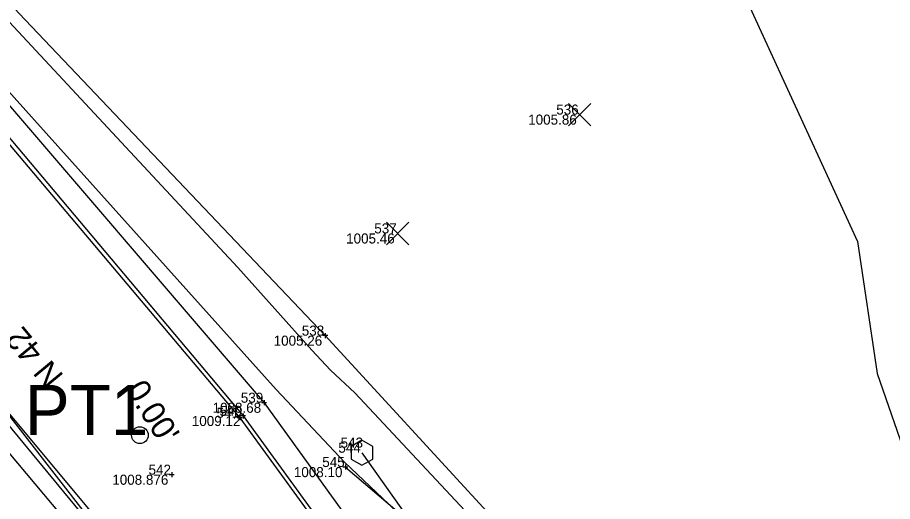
# Model space of a CAD drawing. Extents: x 2354693 to 2355622, y 637071 to 710080.
# Drawn here: x 2355257.5 to 2355361.9, y 709433.1 to 709490.9 of the extents above; entities that cross this region are included whole.
import ezdxf

# ---------------------------------------------------------------- set-up
doc = ezdxf.new("R2010")
doc.units = 0
for name, color, linetype in [('Default', 7, 'Continuous'), ('DT_X_Contour_Minor', 7, 'Continuous'), ('PM_X_Surveyed_Line', 7, 'Continuous'), ('PV_X_EOP', 7, 'Continuous'), ('PV_X_Shoulder', 7, 'Continuous'), ('RD_X_Cells', 7, 'Continuous'), ('RD_X_GR_Lt', 7, 'Continuous'), ('SV_X_Random_Point', 7, 'Continuous'), ('SV_X_Shot_Marker', 7, 'Continuous'), ('SV_X_Text_Elevation', 7, 'Continuous'), ('SV_X_Text_Name', 7, 'Continuous'), ('SV_X_Toe_of_Slope', 7, 'Continuous'), ('SV_X_Top_of_Bank', 7, 'Continuous')]:
    doc.layers.add(name, color=color, linetype=linetype)

msp = doc.modelspace()

# ---------------------------------------------------------------- linework, layer by layer
at = {"layer": 'Default'}
msp.add_line((2355272.1, 709441.07), (2355272.1, 709441.07), dxfattribs=at)
msp.add_line((2355272.1, 709441.07), (2355272.1, 709441.07), dxfattribs=at)
msp.add_line((2355272.1, 709441.07), (2355272.1, 709441.07), dxfattribs=at)
msp.add_line((2355272.1, 709441.07), (2355272.1, 709441.07), dxfattribs=at)
msp.add_line((2355272.1, 709441.07), (2355272.1, 709441.07), dxfattribs=at)
msp.add_line((2355272.1, 709441.07), (2355272.1, 709441.07), dxfattribs=at)
msp.add_line((2355272.1, 709441.07), (2355272.1, 709441.07), dxfattribs=at)
msp.add_line((2355272.1, 709441.07), (2355272.1, 709441.07), dxfattribs=at)
msp.add_line((2355272.1, 709441.07), (2355272.1, 709441.07), dxfattribs=at)
msp.add_circle((2355272.1, 709441.07), 1, dxfattribs=at)
msp.add_circle((2355272.1, 709441.07), 1, dxfattribs=at)
msp.add_circle((2355272.1, 709441.07), 1, dxfattribs=at)
msp.add_circle((2355272.1, 709441.07), 1, dxfattribs=at)
msp.add_circle((2355272.1, 709441.07), 1, dxfattribs=at)
msp.add_circle((2355272.1, 709441.07), 1, dxfattribs=at)
at = {"layer": 'DT_X_Contour_Minor'}
for points in [[(2355344.22, 709493.66), (2355357.75, 709464.2), (2355360.11, 709448.43), (2355366.16, 709430.88), (2355356.05, 709415.12), (2355353.08, 709410.6), (2355352.99, 709409.49), (2355367.98, 709382.49)], [(2355344.22, 709493.66), (2355357.75, 709464.2), (2355360.11, 709448.43), (2355366.16, 709430.88), (2355356.05, 709415.12), (2355353.08, 709410.6), (2355352.99, 709409.49), (2355367.98, 709382.49)], [(2355256.51, 709490.43), (2355283.78, 709461.07), (2355292.63, 709451.21), (2355294.84, 709448.84), (2355297.75, 709446.11), (2355326.87, 709414.97), (2355331.39, 709409.92), (2355333.44, 709407.02), (2355350.91, 709376.42), (2355352.7, 709372.84), (2355354.66, 709368.36), (2355356.55, 709363.93), (2355356.79, 709361.93), (2355357.35, 709361.56), (2355357.12, 709361.28), (2355355.25, 709356.87), (2355352.27, 709351.48), (2355351.87, 709350.82), (2355351.59, 709350.68), (2355350.01, 709351.03), (2355346.35, 709350.2), (2355339.67, 709347.25)], [(2355256.51, 709490.43), (2355283.78, 709461.07), (2355292.63, 709451.21), (2355294.84, 709448.84), (2355297.75, 709446.11), (2355326.87, 709414.97), (2355331.39, 709409.92), (2355333.44, 709407.02), (2355350.91, 709376.42), (2355352.7, 709372.84), (2355354.66, 709368.36), (2355356.55, 709363.93), (2355356.79, 709361.93), (2355357.35, 709361.56), (2355357.12, 709361.28), (2355355.25, 709356.87), (2355352.27, 709351.48), (2355351.87, 709350.82), (2355351.59, 709350.68), (2355350.01, 709351.03), (2355346.35, 709350.2), (2355339.67, 709347.25)], [(2355255.69, 709482.93), (2355288.36, 709446.53), (2355296.54, 709437.79), (2355301.82, 709432.82), (2355307.38, 709427.21), (2355308.61, 709426.12), (2355326.35, 709406.29), (2355335.67, 709393.09), (2355342.8, 709380.62), (2355351.9, 709362.5), (2355353.98, 709357.74), (2355354.28, 709357.38), (2355355.42, 709358.01), (2355354.11, 709354.92), (2355352.33, 709351.68), (2355351.81, 709350.84), (2355351.64, 709350.76), (2355349.63, 709351.21), (2355344.98, 709350.15), (2355336.48, 709346.39)], [(2355255.69, 709482.93), (2355288.36, 709446.53), (2355296.54, 709437.79), (2355301.82, 709432.82), (2355307.38, 709427.21), (2355308.61, 709426.12), (2355326.35, 709406.29), (2355335.67, 709393.09), (2355342.8, 709380.62), (2355351.9, 709362.5), (2355353.98, 709357.74), (2355354.28, 709357.38), (2355355.42, 709358.01), (2355354.11, 709354.92), (2355352.33, 709351.68), (2355351.81, 709350.84), (2355351.64, 709350.76), (2355349.63, 709351.21), (2355344.98, 709350.15), (2355336.48, 709346.39)], [(2355265.88, 709431.37), (2355234.82, 709471.31)], [(2355265.88, 709431.37), (2355234.82, 709471.31)]]:
    msp.add_lwpolyline(points, dxfattribs=at)
at = {"layer": 'PM_X_Surveyed_Line'}
for points in [[(2355180.15, 709561.24), (2355214.75, 709522.89), (2355249.31, 709484.27), (2355284.02, 709443.14), (2355315.55, 709399.77), (2355328.89, 709377.57), (2355342.97, 709349.79), (2355353.37, 709324.19), (2355361.35, 709299.65), (2355367.76, 709272.47), (2355372.19, 709243.49), (2355373.87, 709217.88), (2355371.21, 709164.41), (2355367.13, 709139.62), (2355360.06, 709111.88), (2355351.62, 709085.78), (2355342.5, 709062.34), (2355329.45, 709031.42), (2355320.62, 709012.58)], [(2355165.86, 709547.27), (2355199.55, 709510.04), (2355233.99, 709470.59), (2355267.54, 709430.37), (2355282.6, 709410.56), (2355297.68, 709388.57), (2355309.4, 709369.45), (2355323.83, 709342.43), (2355334.06, 709318.38), (2355342.29, 709293.43), (2355348.47, 709267.17), (2355351.87, 709240.38), (2355352.96, 709217.38), (2355352.46, 709191.09), (2355350.19, 709167.62), (2355345.96, 709144.01), (2355339.85, 709117.86), (2355332.1, 709093.74), (2355322.6, 709069.08), (2355314.61, 709050.66), (2355300.36, 709021.7)]]:
    msp.add_lwpolyline(points, dxfattribs=at)
at = {"layer": 'PV_X_EOP'}
for points in [[(2355180.81, 709561.74), (2355215.64, 709523.56), (2355249.92, 709484.36), (2355284.41, 709443.36), (2355315.94, 709399.97), (2355329.75, 709378.36), (2355343.52, 709350.1), (2355349.22, 709351.4), (2355359.3, 709326.8), (2355367.59, 709301.75), (2355374.11, 709275.91), (2355368.17, 709272.69), (2355372.5, 709243.56), (2355374.5, 709217.66), (2355371.41, 709164.43), (2355367.84, 709139.33), (2355361.02, 709111.64), (2355352.39, 709085.56), (2355343.44, 709061.97), (2355330.49, 709031.08), (2355321.14, 709011.8)], [(2355165.32, 709546.95), (2355198.99, 709509.5), (2355233.4, 709470.11), (2355266.73, 709429.76), (2355281.93, 709410.08), (2355297.05, 709388.17), (2355308.64, 709369.04), (2355321.45, 709342.93), (2355321.34, 709342.62), (2355331.82, 709317.68), (2355340.04, 709292.97), (2355346.6, 709266.72), (2355349.96, 709239.9), (2355351.76, 709217.38), (2355351.56, 709190.76), (2355349.32, 709167.66), (2355345.61, 709144.12), (2355339.52, 709118.01), (2355331.95, 709093.67), (2355322.31, 709069.24), (2355314.27, 709051.11), (2355300.29, 709022.25)]]:
    msp.add_lwpolyline(points, dxfattribs=at)
at = {"layer": 'PV_X_Shoulder'}
for points in [[(2355182.19, 709563.22), (2355217.16, 709524.65), (2355251.59, 709486.13), (2355286.91, 709444.94), (2355318.24, 709401.51), (2355331.47, 709379.67), (2355345.37, 709350.94)], [(2355163.76, 709545.77), (2355197.77, 709507.92), (2355231.62, 709468.51), (2355264.91, 709428.85), (2355280.65, 709409.06), (2355295.99, 709387.67), (2355307.78, 709368.44), (2355321.17, 709342.6)]]:
    msp.add_lwpolyline(points, dxfattribs=at)
at = {"layer": 'RD_X_Cells'}
msp.add_lwpolyline([(2355297.31, 709438.22), (2355298.6, 709437.47), (2355299.9, 709438.22), (2355299.9, 709439.72), (2355298.6, 709440.47), (2355297.31, 709439.72), (2355297.31, 709438.22)], dxfattribs=at)
at = {"layer": 'RD_X_GR_Lt'}
msp.add_lwpolyline([(2355298.6, 709438.97), (2355313.71, 709417.64), (2355322.76, 709404.11), (2355335.4, 709382.17), (2355349.98, 709350.52)], dxfattribs=at)
at = {"layer": 'SV_X_Random_Point'}
for p, q in [((2355323.26, 709478), (2355325.92, 709480.67)), ((2355323.26, 709480.67), (2355325.92, 709478)), ((2355301.52, 709463.81), (2355304.19, 709466.48)), ((2355301.52, 709466.48), (2355304.19, 709463.81))]:
    msp.add_line(p, q, dxfattribs=at)
at = {"layer": 'SV_X_Shot_Marker'}
for p, q in [((2355294.51, 709452.95), (2355293.91, 709452.95)), ((2355294.21, 709453.25), (2355294.21, 709452.65)), ((2355287.21, 709444.94), (2355286.61, 709444.94)), ((2355286.91, 709445.24), (2355286.91, 709444.64)), ((2355284.02, 709443.44), (2355284.02, 709442.84)), ((2355284.71, 709443.36), (2355284.11, 709443.36)), ((2355284.41, 709443.66), (2355284.41, 709443.06)), ((2355284.32, 709443.14), (2355283.72, 709443.14)), ((2355296.93, 709437.26), (2355296.33, 709437.26)), ((2355296.63, 709437.56), (2355296.63, 709436.96)), ((2355276.2, 709436.35), (2355275.6, 709436.35)), ((2355275.9, 709436.65), (2355275.9, 709436.05))]:
    msp.add_line(p, q, dxfattribs=at)
at = {"layer": 'SV_X_Toe_of_Slope'}
msp.add_lwpolyline([(2355187.56, 709568.55), (2355223.43, 709529.36), (2355257.66, 709491.43), (2355294.21, 709452.95), (2355332.81, 709410.94), (2355352.9, 709375.39), (2355357.05, 709369.03), (2355359.18, 709363.17)], dxfattribs=at)
at = {"layer": 'SV_X_Top_of_Bank'}
msp.add_lwpolyline([(2355296.63, 709437.26), (2355306.81, 709428.56), (2355324.3, 709404.81), (2355337.21, 709383.51), (2355351.16, 709353.01)], dxfattribs=at)

# ---------------------------------------------------------------- texts
at = {"layer": 'Default'}
for s, rotation, p in [('N 42%%d 39\' 45" W', 129.6098, (2355263.1, 709448.16)), ("0.00'", 302.5665, (2355270.3, 709446.49))]:
    msp.add_text(s, height=2.8, rotation=rotation, dxfattribs=at).set_placement(p)
at = {"layer": 'SV_X_Text_Elevation'}
for s, p in [('1005.86', (2355318.44, 709478.14)), ('1005.46', (2355296.71, 709463.95)), ('1005.26', (2355288.06, 709451.75)), ('1008.68', (2355280.77, 709443.74)), ('1009.12', (2355278.29, 709442.16)), ('1008.10', (2355290.47, 709436.06)), ('1008.876', (2355268.8, 709435.15))]:
    msp.add_text(s, height=1.2, dxfattribs=at).set_placement(p)
at = {"layer": 'SV_X_Text_Name'}
for s, height, p in [('536', 1.2, (2355321.79, 709479.34)), ('537', 1.2, (2355300.07, 709465.15)), ('538', 1.2, (2355291.42, 709452.95)), ('PT1', 6, (2355258.37, 709441.07)), ('539', 1.2, (2355284.14, 709444.94)), ('541', 1.2, (2355281.25, 709443.14)), ('540', 1.2, (2355281.6, 709443.36)), ('544', 1.2, (2355295.78, 709438.97)), ('543', 1.2, (2355296.05, 709439.58)), ('545', 1.2, (2355293.86, 709437.26)), ('542', 1.2, (2355273.13, 709436.35))]:
    msp.add_text(s, height=height, dxfattribs=at).set_placement(p)

doc.saveas('drawing.dxf')
